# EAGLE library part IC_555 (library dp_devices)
Classic 555 IC
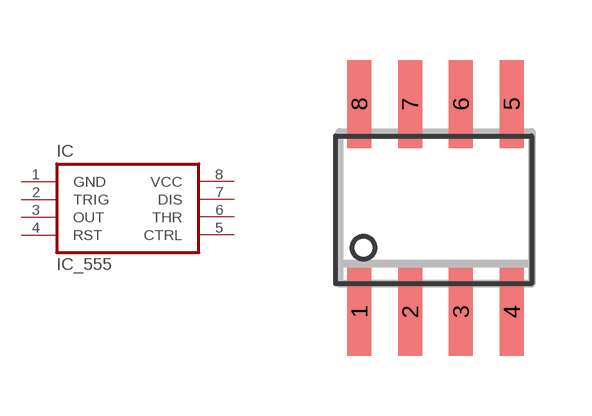
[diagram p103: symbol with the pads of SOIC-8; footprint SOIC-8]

Designator prefix IC

## IC_555-SOIC8  [SOIC-8]
1  GND  sup
2  TRIG  in
3  OUT  out
4  RST  in
5  CTRL  sup
6  THR  in
7  DIS  in
8  VCC  sup

## Footprint SOIC-8 (pad centres in mm)
smd 0.6 x 2.2: 1 -1.905,-2.6; 2 -0.635,-2.6; 3 0.635,-2.6; 4 1.905,-2.6; 5 1.905,2.6; 6 0.635,2.6; 7 -0.635,2.6; 8 -1.905,2.6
